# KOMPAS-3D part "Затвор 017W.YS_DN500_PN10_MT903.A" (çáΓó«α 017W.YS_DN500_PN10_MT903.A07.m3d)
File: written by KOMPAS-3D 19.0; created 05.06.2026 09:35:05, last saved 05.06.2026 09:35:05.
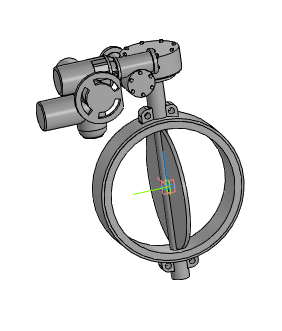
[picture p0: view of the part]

Document properties: Автор: Энергия; Полное имя файла: ..\..\..\3d для проектировщиков\x.x Тип 017W.Y(S) Затвор дисковый поворотный межфланцевый\Затвор 017W.Y(S)_DN32-DN1200_QT.A_MT903.A\Затвор 017W.YS_DN500_MT903.A07.a3d

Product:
- Part/product: Затвор 017W.YS_DN500_PN10_MT903.A
    Масса: 222.809

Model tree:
1. Операция без истории:1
